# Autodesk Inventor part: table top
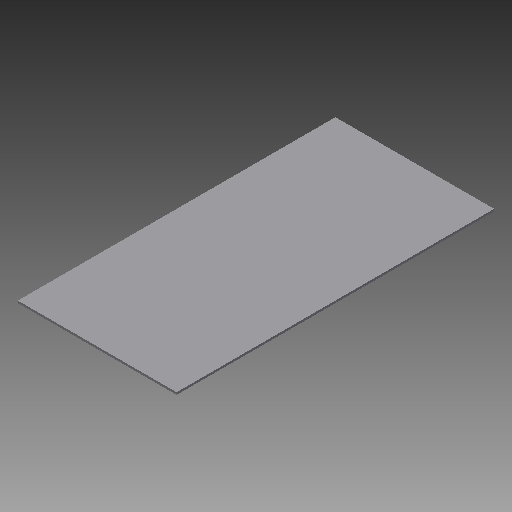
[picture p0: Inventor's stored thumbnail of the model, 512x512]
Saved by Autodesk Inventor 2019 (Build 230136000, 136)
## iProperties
Created: 2013-07
Part Number: table top
Material: Generic
Document SubType Name: Modeling
Designer: Patrick Rice
Density: 1 g/cm^3
Appearance: Default
Author: Patrick Rice
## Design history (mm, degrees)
sketch "Sketch1"
  geometry: L1 (457.2, -914.4)-(-457.2, -914.4); L2 (-457.2, -914.4)-(-457.2, 914.4); L3 (-457.2, 914.4)-(457.2, 914.4); L4 (457.2, 914.4)-(457.2, -914.4); L5 (457.2, -914.4)-(-457.2, 914.4); L6 (-457.2, -914.4)-(457.2, 914.4); L7 (76.2, -914.4)-(-12.7, -914.4); L8 (-12.7, 914.4)-(76.2, 914.4); 1 further point
  constraints: 16 end point, 3 horizontal, 2 midpoint, 2 parallel, 2 point on line, 1 perpendicular
  dimensions: "d0" = 914.4 distance of L2.end L3.end; "d1" = 1828.8 distance of L1.end L2.end
extrude "Extrusion3" new body sketch "Sketch1" distance "d16" = 12.7; taper "d17" = 0 deg
body "Solid3"
